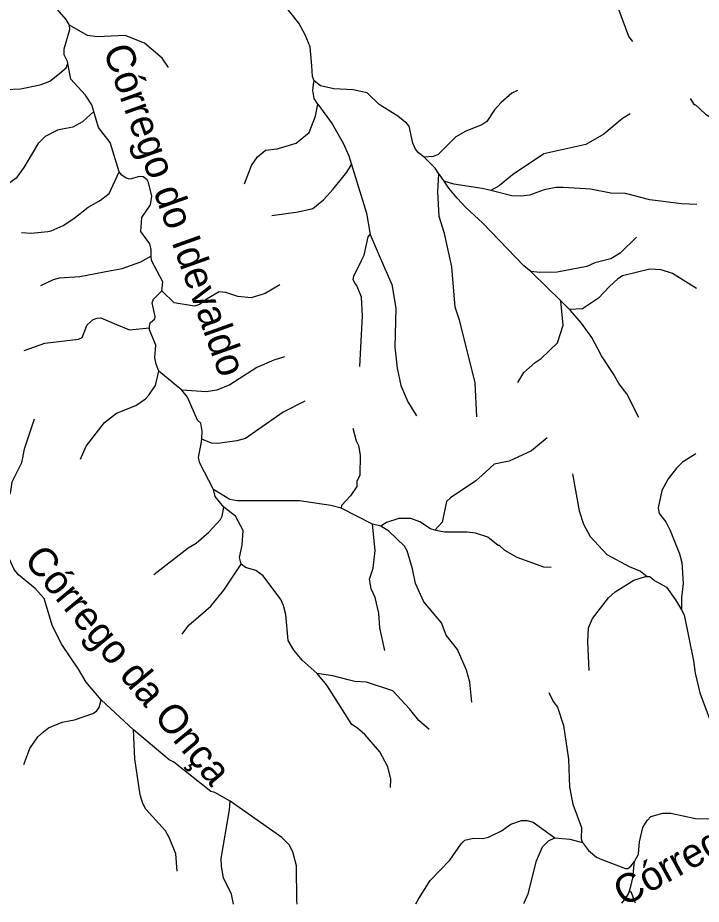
# Model space of a CAD drawing. Extents: x 393 to 446.6, y 8175.5 to 8231.
# Drawn here: x 436.819 to 440.612, y 8175.645 to 8180.565 of the extents above; entities that cross this region are included whole.
import ezdxf
from ezdxf.enums import TextEntityAlignment as Align

# ---------------------------------------------------------------- set-up
doc = ezdxf.new("R2010")
doc.units = 0
doc.header["$LTSCALE"] = 0.064
doc.linetypes.add('LONG_DASHED', pattern=[7.5, 6, -1.5])
doc.layers.add('61', color=7, linetype='Continuous')
doc.layers.add('7', color=7, linetype='Continuous', lineweight=25)
doc.layers.add('9', color=7, linetype='LONG_DASHED', lineweight=25)

msp = doc.modelspace()

# ---------------------------------------------------------------- linework, layer by layer
at = {"layer": '7'}
for points in [[(440.2329, 8180.4338), (440.2096, 8180.4606), (440.1483, 8180.6255), (440.116, 8180.6868), (440.1128, 8180.7078), (440.1321, 8180.787), (440.2021, 8180.9469)], [(440.5499, 8180.1167), (440.5721, 8180.0818), (440.5778, 8180.0829), (440.636, 8180.0296), (440.6828, 8180.0021), (440.812, 8179.9472), (440.8685, 8179.9408), (440.9057, 8179.9537), (441.0026, 8179.9424), (441.1317, 8179.9036), (441.2448, 8179.9101), (441.2965, 8179.8859), (441.3723, 8179.7938), (441.4184, 8179.7987)], [(440.582, 8178.1443), (440.5075, 8178.0978), (440.4745, 8178.066), (440.4277, 8178.0063), (440.3937, 8177.9417), (440.3728, 8177.8448), (440.3792, 8177.8141), (440.4147, 8177.7673), (440.439, 8177.7188), (440.4906, 8177.5897), (440.5035, 8177.5412), (440.5116, 8177.425), (440.5019, 8177.3474), (440.5019, 8177.2797), (440.5019, 8177.2781)], [(439.8977, 8178.0336), (439.9351, 8177.8287), (439.9594, 8177.7544), (439.9965, 8177.6865), (440.0885, 8177.5864), (440.2113, 8177.5202), (440.2759, 8177.4927), (440.3119, 8177.464)], [(439.9896, 8176.9427), (439.9836, 8177.102), (439.9868, 8177.1795), (440.0094, 8177.2312), (440.0982, 8177.3458), (440.1338, 8177.3781), (440.2387, 8177.4443), (440.3019, 8177.464), (440.3119, 8177.464)], [(440.3119, 8177.464), (440.3275, 8177.464), (440.3518, 8177.4411), (440.4196, 8177.404), (440.4696, 8177.3345), (440.5019, 8177.2781)], [(440.5019, 8177.2781), (440.517, 8177.2517), (440.5698, 8176.9954), (440.5778, 8176.9276), (440.6037, 8176.8178), (440.6909, 8176.5853), (440.6997, 8176.5656), (440.7571, 8176.4367), (440.7917, 8176.3738), (440.7926, 8176.3722)], [(439.7662, 8176.8208), (439.7907, 8176.7708), (439.814, 8176.7386), (439.8479, 8176.6369), (439.8754, 8176.4496), (439.8802, 8176.2946), (439.8996, 8176.2009), (439.9481, 8176.0718), (439.9448, 8176.0088), (439.9537, 8175.9875)], [(439.0274, 8175.6477), (439.0454, 8175.6763), (439.1084, 8175.7762), (439.1635, 8175.8338), (439.2166, 8175.8893), (439.2795, 8175.9797), (439.3005, 8176.0007), (439.349, 8176.012), (439.4007, 8176.0104), (439.4314, 8176.0168), (439.504, 8176.0523), (439.5557, 8176.0895), (439.6138, 8176.1105), (439.6461, 8176.1105), (439.6784, 8176.1008), (439.7995, 8176.014)], [(440.2419, 8175.8816), (440.2646, 8175.9232), (440.2694, 8175.991), (440.2872, 8176.0718), (440.3114, 8176.1105), (440.3324, 8176.1315), (440.3986, 8176.1508), (440.4438, 8176.1508), (440.5795, 8176.1202), (440.6441, 8176.1185), (440.6635, 8176.1218), (440.705, 8176.1419)], [(439.6275, 8175.6494), (439.6293, 8175.6536), (439.6509, 8175.7036), (439.6987, 8175.8865), (439.7313, 8175.9645), (439.764, 8175.9975), (439.7995, 8176.014)], [(439.7995, 8176.014), (439.8819, 8176.0055), (439.9537, 8175.9875)], [(439.9537, 8175.9875), (439.9868, 8175.9426), (440.0305, 8175.9054), (440.0601, 8175.8941), (440.1919, 8175.844), (440.2049, 8175.844), (440.2217, 8175.8558), (440.2419, 8175.8816)], [(440.2133, 8175.7192), (440.221, 8175.743), (440.2326, 8175.7907), (440.2419, 8175.8816)], [(440.1723, 8175.651), (440.1872, 8175.672), (440.207, 8175.6999), (440.2133, 8175.7192)], [(440.2481, 8175.6512), (440.2419, 8175.6662), (440.2245, 8175.7081), (440.214, 8175.7185), (440.2133, 8175.7192)]]:
    msp.add_lwpolyline(points, dxfattribs=at)
at = {"layer": '9'}
for p, q in [((439.8817, 8178.9459), (439.8322, 8178.9944)), ((437.7285, 8178.4985), (437.6016, 8178.6033)), ((438.7874, 8177.7543), (438.614, 8177.8433)), ((438.834, 8177.7427), (438.7874, 8177.7543)), ((437.4615, 8176.6134), (437.281, 8176.7799))]:
    msp.add_line(p, q, dxfattribs=at)
for points in [[(437.1052, 8180.5234), (437.0877, 8180.5549), (437.0237, 8180.627), (436.9887, 8180.7003), (436.934, 8180.791), (436.9268, 8180.9307), (436.888, 8181.0356), (436.8622, 8181.0728), (436.783, 8181.1354)], [(438.4641, 8180.2142), (438.4548, 8180.2386), (438.4501, 8180.2983), (438.442, 8180.4027), (438.414, 8180.4705), (438.3785, 8180.535), (438.251, 8180.6981)], [(437.0965, 8180.3113), (437.0946, 8180.3216), (437.0772, 8180.3588), (437.0772, 8180.3926), (437.1075, 8180.499), (437.1052, 8180.5234)], [(437.6549, 8180.289), (437.6195, 8180.3412), (437.5227, 8180.4236), (437.4145, 8180.4656), (437.2595, 8180.4591), (437.2062, 8180.4672), (437.1052, 8180.5234)], [(436.5961, 8180.1461), (436.6486, 8180.1676), (436.662, 8180.1636), (436.8348, 8180.1701), (436.9342, 8180.1911), (436.9494, 8180.1943), (436.9962, 8180.2137), (437.0511, 8180.2556), (437.0883, 8180.2863), (437.0965, 8180.3113)], [(437.241, 8180.0438), (437.2298, 8180.0814), (437.1988, 8180.1292), (437.1932, 8180.1378), (437.1125, 8180.225), (437.0965, 8180.3113)], [(438.4846, 8180.0856), (438.4629, 8180.1165), (438.456, 8180.1604), (438.4594, 8180.1969), (438.4641, 8180.2142)], [(439.0741, 8179.792), (439.0427, 8179.8147), (439.026, 8179.8358), (439.0115, 8179.8698), (438.9905, 8179.9634), (438.9776, 8179.9779), (438.9275, 8180.0183), (438.8242, 8180.0829), (438.758, 8180.1491), (438.7222, 8180.1565), (438.6805, 8180.1652), (438.5723, 8180.1701), (438.4996, 8180.1878), (438.4641, 8180.2142)], [(439.5928, 8180.1621), (439.5614, 8180.1458), (439.5008, 8180.0942), (439.4652, 8180.0538), (439.4217, 8179.9892), (439.3942, 8179.9698), (439.3054, 8179.9359), (439.2505, 8179.9036), (439.152, 8179.8051), (439.1245, 8179.7954), (439.0741, 8179.792)], [(438.078, 8179.6436), (438.1153, 8179.7454), (438.1492, 8179.7922), (438.1799, 8179.8197), (438.1944, 8179.8293), (438.259, 8179.8375), (438.364, 8179.8697), (438.4366, 8179.9279), (438.4705, 8180.0183), (438.4846, 8180.0856)], [(438.4846, 8180.0856), (438.5642, 8179.9763), (438.6256, 8179.8681), (438.6554, 8179.798), (438.6704, 8179.7501)], [(436.6586, 8179.6162), (436.7565, 8179.6383), (436.8147, 8179.6802), (436.8543, 8179.7331), (436.9359, 8179.8716), (436.9736, 8179.9069), (437.0414, 8179.9424), (437.0661, 8179.9476), (437.1254, 8179.9602), (437.1803, 8179.9892), (437.241, 8180.0438)], [(437.3822, 8179.7102), (437.3311, 8179.8719), (437.2671, 8179.9557), (437.241, 8180.0438)], [(440.2179, 8180.0323), (440.1757, 8180.0054), (440.0724, 8179.9182), (439.9723, 8179.8617), (439.7382, 8179.81), (439.5654, 8179.6937), (439.4911, 8179.6323), (439.4439, 8179.6056)], [(438.2285, 8179.4678), (438.3741, 8179.4875), (438.456, 8179.5064), (438.5157, 8179.5549), (438.5691, 8179.613), (438.6449, 8179.7082), (438.6704, 8179.7501)], [(438.6704, 8179.7501), (438.7548, 8179.4806), (438.7741, 8179.3627)], [(439.1552, 8179.6988), (439.1346, 8179.7306), (439.0741, 8179.792)], [(436.8389, 8179.3732), (436.8937, 8179.3697), (436.985, 8179.3788), (437.0043, 8179.3821), (437.0705, 8179.4127), (437.1303, 8179.4515), (437.2094, 8179.5145), (437.2691, 8179.5478), (437.2788, 8179.5532), (437.3257, 8179.5888), (437.3822, 8179.7102)], [(437.56, 8179.2434), (437.5598, 8179.2787), (437.5517, 8179.311), (437.5017, 8179.3789), (437.5065, 8179.4564), (437.5549, 8179.5274), (437.5631, 8179.5742), (437.5452, 8179.6501), (437.5372, 8179.6663), (437.5146, 8179.6824), (437.4952, 8179.684), (437.4416, 8179.6695), (437.4195, 8179.6753), (437.3962, 8179.6916), (437.3822, 8179.7102)], [(439.3664, 8178.3498), (439.3571, 8178.5392), (439.2731, 8178.8815), (439.2456, 8178.959), (439.2279, 8179.1818), (439.1875, 8179.3675), (439.1584, 8179.4628), (439.1503, 8179.5985), (439.1552, 8179.6988)], [(439.1861, 8179.6578), (439.1591, 8179.6943), (439.1552, 8179.6988)], [(439.4439, 8179.6056), (439.3958, 8179.6178), (439.2392, 8179.642), (439.1861, 8179.6578)], [(439.6658, 8179.1562), (439.6267, 8179.1883), (439.399, 8179.4273), (439.307, 8179.5096), (439.257, 8179.5645), (439.2104, 8179.6194), (439.1861, 8179.6578)], [(440.5885, 8179.5287), (440.502, 8179.5322), (440.3276, 8179.5549), (440.1919, 8179.5887), (440.1096, 8179.592), (439.9982, 8179.613), (439.8464, 8179.6226), (439.8044, 8179.6226), (439.7398, 8179.6097), (439.6591, 8179.5807), (439.6138, 8179.5742), (439.5605, 8179.5759), (439.4439, 8179.6056)], [(438.7174, 8178.6302), (438.7321, 8178.9106), (438.7273, 8179.0139), (438.7192, 8179.0323), (438.7063, 8179.0639), (438.6998, 8179.0785), (438.6901, 8179.093), (438.6807, 8179.1107), (438.6836, 8179.1311), (438.7268, 8179.2168), (438.7418, 8179.2464), (438.7644, 8179.3498), (438.7741, 8179.3627)], [(438.7741, 8179.3627), (438.8309, 8179.2325), (438.8952, 8179.085), (438.9178, 8178.9525), (438.9114, 8178.7362), (438.9243, 8178.6199), (438.9453, 8178.5246), (438.984, 8178.4326), (439.0316, 8178.3558)], [(440.252, 8179.3481), (440.1628, 8179.2577), (440.1096, 8179.2271), (440.0224, 8179.2045), (439.9772, 8179.1851), (439.8124, 8179.1528), (439.7172, 8179.1511), (439.666, 8179.1562), (439.6658, 8179.1562)], [(436.9464, 8179.0781), (437.0172, 8179.1124), (437.0511, 8179.1221), (437.1626, 8179.1285), (437.3363, 8179.1618), (437.3983, 8179.1737), (437.5017, 8179.2109), (437.558, 8179.2423), (437.56, 8179.2434)], [(437.6183, 8179.0485), (437.623, 8179.0985), (437.5601, 8179.2184), (437.56, 8179.2434)], [(440.5851, 8179.0617), (440.4535, 8179.1463), (440.3889, 8179.1657), (440.3259, 8179.1689), (440.1758, 8179.1317), (440.1487, 8179.1165), (440.1031, 8179.0736), (440.0417, 8179.0091), (439.9529, 8178.9493), (439.8818, 8178.9459), (439.8817, 8178.9459)], [(439.8322, 8178.9944), (439.6737, 8179.1497), (439.6658, 8179.1562)], [(438.2729, 8179.0823), (438.1912, 8179.0349), (438.1137, 8179.0107), (438.041, 8179.0171), (437.9732, 8179.0397), (437.9361, 8179.043), (437.8698, 8179.0058), (437.8278, 8178.9735), (437.7988, 8178.9638), (437.6873, 8178.9832), (437.6183, 8179.0485)], [(437.5507, 8178.8443), (437.5507, 8178.8536), (437.5542, 8178.871), (437.5787, 8178.8943), (437.5822, 8178.9071), (437.5647, 8178.9827), (437.5717, 8179.0037), (437.6183, 8179.0485)], [(439.595, 8178.5408), (439.6268, 8178.5957), (439.6913, 8178.6522), (439.7236, 8178.6731), (439.814, 8178.7603), (439.8463, 8178.8589), (439.8322, 8178.9944)], [(440.2657, 8178.3468), (440.1984, 8178.4778), (440.1548, 8178.5343), (440.1241, 8178.5908), (440.0579, 8178.6893), (440.0046, 8178.7911), (439.9481, 8178.8702), (439.8868, 8178.9409), (439.8817, 8178.9459)], [(436.855, 8178.7178), (436.9688, 8178.7587), (437.1561, 8178.7813), (437.1771, 8178.7911), (437.2045, 8178.8605), (437.2368, 8178.8895), (437.2595, 8178.8976), (437.2804, 8178.8992), (437.3666, 8178.8632), (437.4387, 8178.8331), (437.5507, 8178.8443)], [(437.6016, 8178.6033), (437.5877, 8178.6423), (437.5792, 8178.678), (437.5857, 8178.7475), (437.5507, 8178.8338), (437.5507, 8178.8443)], [(438.2993, 8178.6825), (438.2399, 8178.665), (438.1456, 8178.6231), (437.9954, 8178.5283), (437.9233, 8178.4986), (437.865, 8178.4893), (437.7285, 8178.4985)], [(437.1662, 8178.1149), (437.1989, 8178.1876), (437.2998, 8178.3195), (437.3676, 8178.3696), (437.4742, 8178.4132), (437.5275, 8178.4503), (437.5453, 8178.4697), (437.5734, 8178.5113), (437.5824, 8178.5246), (437.6016, 8178.6033)], [(437.8401, 8178.2271), (437.8426, 8178.2712), (437.8343, 8178.3147), (437.8166, 8178.3325), (437.76, 8178.4584), (437.7285, 8178.4985)], [(438.4113, 8178.4379), (438.2913, 8178.3761), (438.083, 8178.2307), (438.0346, 8178.2178), (437.9297, 8178.2021), (437.8948, 8178.2044), (437.8403, 8178.227), (437.8401, 8178.2271)], [(436.9094, 8178.3369), (436.8541, 8178.171), (436.8396, 8178.0951), (436.7863, 8177.9869), (436.7782, 8177.9352), (436.7653, 8177.8981), (436.7502, 8177.8754), (436.7083, 8177.844), (436.685, 8177.844), (436.6018, 8177.8722)], [(438.6786, 8178.2878), (438.6966, 8178.2162), (438.7095, 8178.1904), (438.7192, 8178.1371), (438.7176, 8178.0257), (438.7014, 8177.9917), (438.6999, 8177.9627), (438.6659, 8177.911), (438.6159, 8177.8577), (438.614, 8177.8433)], [(437.9042, 8177.9461), (437.8294, 8178.0935), (437.8214, 8178.1241), (437.8392, 8178.2113), (437.8401, 8178.2271)], [(439.7575, 8178.2333), (439.6703, 8178.1613), (439.546, 8178.1047), (439.4636, 8178.087), (439.3935, 8178.0236), (439.3619, 8177.9949), (439.2198, 8177.9013), (439.1988, 8177.8803), (439.1746, 8177.7657), (439.1358, 8177.7232), (439.1341, 8177.7214)], [(437.9633, 8177.848), (437.9144, 8177.9074), (437.9141, 8177.9085), (437.9042, 8177.9461)], [(438.614, 8177.8433), (438.5569, 8177.8573), (438.3817, 8177.8836), (438.0362, 8177.8836), (437.9957, 8177.8915), (437.9042, 8177.9461)], [(437.281, 8176.7799), (437.1981, 8176.8775), (437.1561, 8176.9502), (437.064, 8177.0858), (437.0124, 8177.1892), (436.9655, 8177.341), (436.9155, 8177.3975), (436.8234, 8177.4734), (436.7992, 8177.5025), (436.7137, 8177.6881), (436.6018, 8177.8722)], [(437.574, 8177.4755), (437.7649, 8177.6236), (437.8085, 8177.6494), (437.8795, 8177.7091), (437.9441, 8177.7802), (437.9538, 8177.7996), (437.9633, 8177.848)], [(438.0594, 8177.5324), (438.0501, 8177.5697), (438.0636, 8177.6381), (438.0701, 8177.7188), (438.0281, 8177.798), (437.9633, 8177.848)], [(439.1341, 8177.7214), (439.109, 8177.7278), (439.0496, 8177.7674), (439.0002, 8177.785), (438.934, 8177.7867), (438.8646, 8177.764), (438.834, 8177.7427)], [(438.8562, 8177.053), (438.8274, 8177.1795), (438.8226, 8177.2602), (438.8016, 8177.3474), (438.7806, 8177.3959), (438.7709, 8177.4492), (438.7919, 8177.5105), (438.8032, 8177.6074), (438.7874, 8177.7543)], [(439.3389, 8176.7668), (439.328, 8176.8775), (439.3086, 8176.9437), (439.2602, 8177.0584), (439.1956, 8177.1391), (439.1714, 8177.2069), (439.0729, 8177.3232), (439.026, 8177.425), (439.0099, 8177.5073), (438.9792, 8177.6058), (438.9647, 8177.6316), (438.8791, 8177.7156), (438.834, 8177.7427)], [(439.779, 8177.5141), (439.7382, 8177.5154), (439.5896, 8177.5703), (439.5218, 8177.6074), (439.4927, 8177.6364), (439.4846, 8177.6364), (439.4281, 8177.6817), (439.3587, 8177.7043), (439.3135, 8177.7107), (439.1875, 8177.7107), (439.1568, 8177.7156), (439.1341, 8177.7214)], [(437.7303, 8177.1431), (437.7687, 8177.1943), (437.8908, 8177.299), (437.9619, 8177.3878), (438.0594, 8177.5324)], [(438.4798, 8176.9252), (438.3979, 8177.0002), (438.3511, 8177.0551), (438.3203, 8177.1085), (438.3058, 8177.2538), (438.2945, 8177.3022), (438.2784, 8177.3361), (438.1815, 8177.4685), (438.1395, 8177.4976), (438.083, 8177.5137), (438.0594, 8177.5324)], [(438.888, 8176.2934), (438.8892, 8176.34), (438.8726, 8176.4076), (438.8274, 8176.49), (438.745, 8176.5869), (438.7047, 8176.6224), (438.6724, 8176.6418), (438.5335, 8176.8614), (438.4798, 8176.9252)], [(439.1012, 8176.6154), (439.0454, 8176.6643), (438.9938, 8176.729), (438.9001, 8176.829), (438.7548, 8176.8775), (438.6902, 8176.8807), (438.6533, 8176.8904), (438.5674, 8176.913), (438.4798, 8176.9252)], [(436.8516, 8176.4209), (436.8864, 8176.5093), (436.93, 8176.5739), (436.9607, 8176.6014), (436.9898, 8176.624), (437.0657, 8176.6563), (437.1335, 8176.6692), (437.2352, 8176.7031), (437.2549, 8176.7165), (437.2712, 8176.7374), (437.281, 8176.7799)], [(437.7029, 8175.8289), (437.6955, 8175.9248), (437.6615, 8176.012), (437.6389, 8176.0523), (437.5291, 8176.1719), (437.5129, 8176.2042), (437.4984, 8176.2526), (437.4678, 8176.4512), (437.4615, 8176.6134)], [(437.9972, 8176.2165), (437.9118, 8176.2655), (437.8908, 8176.2703), (437.6857, 8176.4335), (437.6599, 8176.4463), (437.4615, 8176.6134)], [(438.0168, 8175.6449), (438.0058, 8175.7003), (437.961, 8175.7915), (437.9489, 8175.8554), (437.9474, 8175.899), (437.9942, 8176.1686), (437.9972, 8176.2165)], [(438.3692, 8175.6459), (438.368, 8175.6639), (438.3656, 8175.8586), (438.3446, 8175.9361), (438.3252, 8175.9748), (438.2848, 8176.0152), (437.9972, 8176.2165)]]:
    msp.add_lwpolyline(points, dxfattribs=at)

# ---------------------------------------------------------------- texts
at = {"layer": '61'}
for s, rotation, p in [('Córrego do Idevaldo', 289.635, (437.6168, 8179.4734)), ('Córrego da Onça', 309.685, (437.371, 8176.9229)), ('Córrego José Manuel', 29.021, (441.0766, 8176.1249))]:
    msp.add_text(s, height=0.16, rotation=rotation, dxfattribs=at).set_placement(p, align=Align.CENTER)

doc.saveas('drawing.dxf')
